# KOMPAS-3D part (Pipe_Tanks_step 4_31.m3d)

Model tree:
1. X Axis
2. Y Axis
3. Z Axis  (labels: Pipe Dn 20; Valve Dy 50)
     Òîëùèíà ñòåíêè 1 = 1

Referenced files in C:\Documents and Settings\kashirsky\Мои документы\Camtasia Studio\Pipelines3D\Tanks\: Tanks_step 4.a3d
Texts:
  Pipe Dn 20
  Steel ASTM A295
  Three Point Plane
  Plane at Angle
  Line and Point Plane
  Axis through Two Vertices
  Axis of Feature
  Axis of Conical Surface
  Axis through Edge
  Trim by Surface
  Trim by Sketch
  Feature with No History
  Intersection Axis of Two Planes
  Two Line Plane
  Line and Face Plane
  Bend by line
  Hole in sheet body
  Cut in sheet body
  Point in CM
  Linear Dimension from Line to Point
  Surface Finish Symbol
  Geometric Tolerance Symbol
  Leader #1
  Leader #2
  Leader #3
  Shape Deviations and Datum
  Node point number
  Mark of coordination axis
  Node point designation
  Mark/Reference designation with leader
  Mark/reference designation on line
  Mark/Reference designation without leader
  Valve Dy 50
  Plane of section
